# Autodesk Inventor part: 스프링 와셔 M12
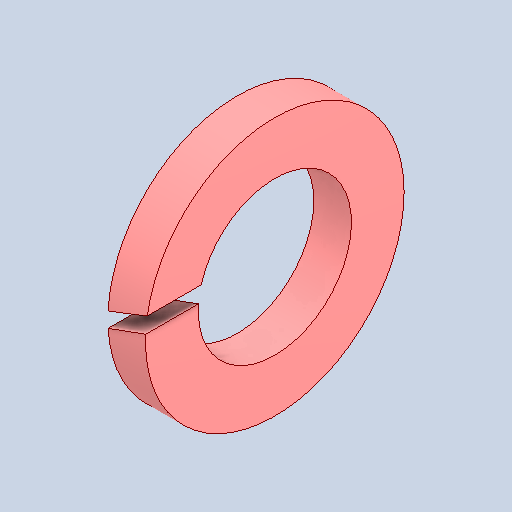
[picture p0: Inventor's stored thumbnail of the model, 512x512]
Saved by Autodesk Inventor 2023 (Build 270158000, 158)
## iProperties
Created: 2025-03
Part Number: 스프링 와셔 M12
Material: 강철, 연강
Description: 스프링 잠금 와셔
Document SubType Name: Modeling
Designer: user
Density: 7.85 g/cm^3
Appearance: 기본값
Author: jhkim
Sending System: Autodesk Inventor 2025
Preprocessor: ST-DEVELOPER v20
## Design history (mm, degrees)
feature "Solid1"
node "솔리드1"
